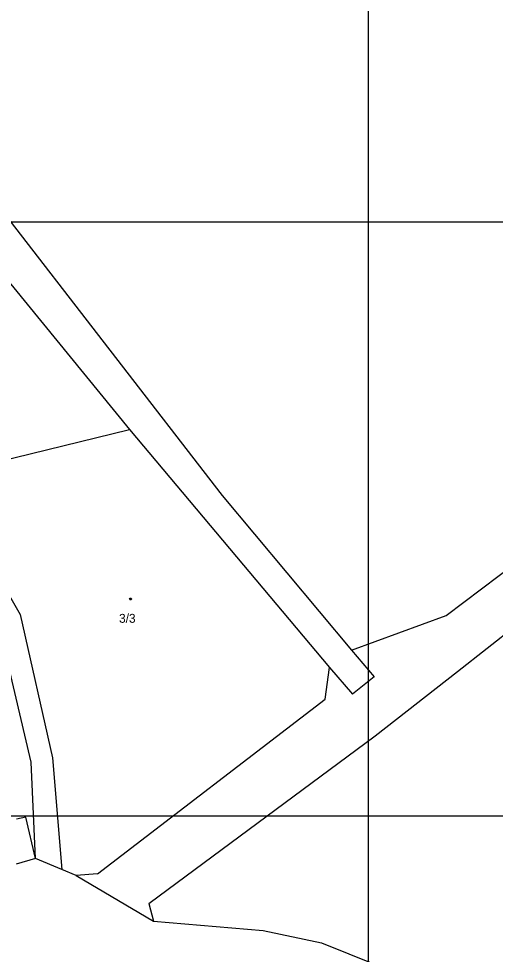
# Model space of a CAD drawing. Extents: x -802857 to -799647, y -1020285 to -1015884.
# Drawn here: x -801316.9 to -801225.7, y -1017640.2 to -1017461.1 of the extents above; entities that cross this region are included whole.
import ezdxf

# ---------------------------------------------------------------- set-up
doc = ezdxf.new("R2010")
doc.units = 0
for name, color, linetype in [('Default', 7, 'Continuous'), ('KLADY_ZMVM', 7, 'Continuous'), ('KN_HRANICE', 7, 'Continuous'), ('KN_KULTURY', 7, 'Continuous'), ('KN_PARCELY', 7, 'Continuous'), ('LEGENDA', 7, 'Continuous')]:
    doc.layers.add(name, color=color, linetype=linetype)

# ---------------------------------------------------------------- blocks, each defined once
blk = doc.blocks.new('NAHRADNI_SYMBOL')
at = {"layer": 'Default'}
blk.add_lwpolyline([(0.09, 0.15), (0.18, 0), (0.09, -0.15), (-0.09, -0.15), (-0.18, 0), (-0.09, 0.15), (0.09, 0.15)], dxfattribs=at)

msp = doc.modelspace()

# ---------------------------------------------------------------- linework, layer by layer
at = {"layer": 'KLADY_ZMVM'}
for points in [[(-801250, -1017000), (-801250, -1017500), (-801250, -1018000)], [(-801875, -1017500), (-801250, -1017500), (-801043.11, -1017500)]]:
    msp.add_lwpolyline(points, dxfattribs=at)
at = {"layer": 'KN_HRANICE'}
for p, q in [((-801235.08, -1017575.37), (-801095.04, -1017469.02)), ((-801324.28, -1017492.5), (-801277.94, -1017552.4)), ((-801330.52, -1017497.1), (-801295.7, -1017539.76)), ((-801337.12, -1017549.87), (-801295.7, -1017539.76)), ((-801295.7, -1017539.76), (-801257.41, -1017585.32)), ((-801277.94, -1017552.4), (-801253.19, -1017581.98)), ((-801324.97, -1017560.63), (-801316.63, -1017575.17)), ((-801232.93, -1017586.06), (-801214.32, -1017571.47)), ((-801316.63, -1017575.17), (-801310.44, -1017602.62)), ((-801314.53, -1017603.45), (-801320.87, -1017576.78)), ((-801253.19, -1017581.98), (-801235.08, -1017575.37)), ((-801253.19, -1017581.98), (-801248.88, -1017587.13)), ((-801258.27, -1017591.39), (-801257.41, -1017585.32)), ((-801257.41, -1017585.32), (-801253, -1017590.46)), ((-801248.88, -1017587.13), (-801253, -1017590.46)), ((-801248.69, -1017598.39), (-801232.93, -1017586.06)), ((-801301.82, -1017624.81), (-801258.27, -1017591.39)), ((-801292.02, -1017630.5), (-801248.69, -1017598.39)), ((-801313.67, -1017621.93), (-801314.53, -1017603.45)), ((-801310.44, -1017602.62), (-801308.63, -1017624.01)), ((-801315.54, -1017613.96), (-801317.34, -1017614.38)), ((-801313.67, -1017621.93), (-801315.54, -1017613.96)), ((-801313.67, -1017621.93), (-801317.37, -1017622.97)), ((-801308.63, -1017624.01), (-801313.67, -1017621.93)), ((-801305.91, -1017625.13), (-801308.63, -1017624.01)), ((-801301.82, -1017624.81), (-801305.91, -1017625.13)), ((-801305.91, -1017625.13), (-801291.14, -1017633.93)), ((-801292.02, -1017630.5), (-801291.14, -1017633.93)), ((-801291.14, -1017633.93), (-801270.14, -1017635.69)), ((-801270.14, -1017635.69), (-801258.97, -1017638.08)), ((-801258.97, -1017638.08), (-801218.75, -1017654.12))]:
    msp.add_line(p, q, dxfattribs=at)
at = {"layer": 'LEGENDA'}
msp.add_lwpolyline([(-801703.84, -1017613.71), (-800862.84, -1017613.71), (-800862.84, -1017019.71), (-801703.84, -1017019.71)], close=True, dxfattribs=at)

# ---------------------------------------------------------------- block references
at = {"layer": 'KN_KULTURY'}
msp.add_blockref('NAHRADNI_SYMBOL', (-801295.5, -1017572.21), dxfattribs=at)

# ---------------------------------------------------------------- texts
at = {"layer": 'KN_PARCELY'}
msp.add_text('3/3', height=1.7, dxfattribs=at).set_placement((-801297.7, -1017576.76))

doc.saveas('drawing.dxf')
